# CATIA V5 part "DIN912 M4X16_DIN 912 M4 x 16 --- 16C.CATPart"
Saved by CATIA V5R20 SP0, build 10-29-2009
Part number: DIN912 M4X16_DIN 912 M4 x 16 --- 16C
Revision: ANY
Definition: UNKNOWN
Nomenclature: DIN912 M4X16_DIN 912 M4 x 16 --- 16C
Source: Unknown
Bounding box of the stored display mesh (mm): x 0 to 20, y -3.329 to 3.329, z -3.5 to 3.5
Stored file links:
  C:\Users\Utente\Desktop\IO LAVORO\3D X SITO CF\CUMSA\3D files CG\CG 603035\DIN912 M4X16_DIN 912 M4 x 16 --- 16C.CATPart
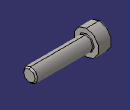
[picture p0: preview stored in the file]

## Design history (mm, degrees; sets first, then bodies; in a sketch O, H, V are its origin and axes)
Body1 "Hex" (main body)
  Solid1: solid without history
